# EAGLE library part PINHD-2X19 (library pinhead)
PIN HEADER
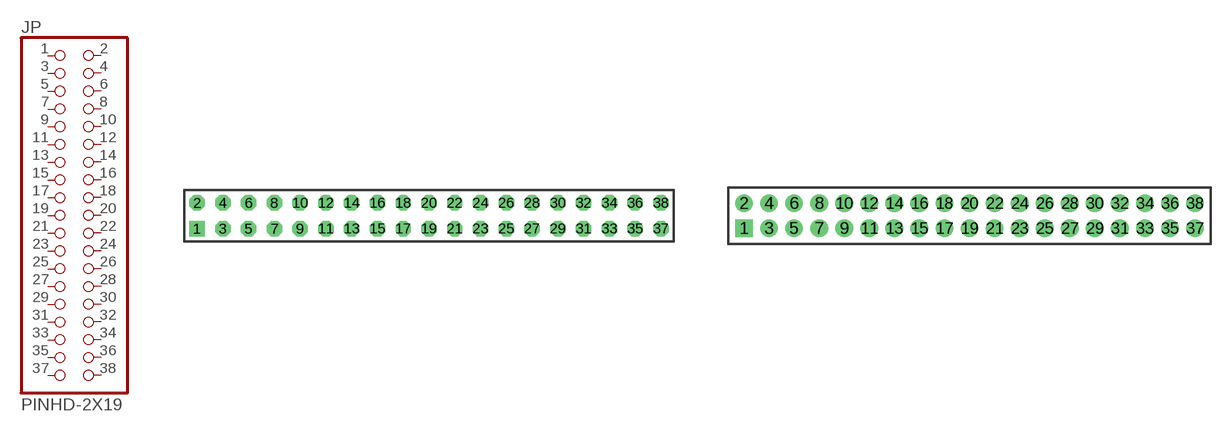
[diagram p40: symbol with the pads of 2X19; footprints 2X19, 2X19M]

Designator prefix JP

## PINHD-2X19  [2X19]
1  1  pas
2  2  pas
3  3  pas
4  4  pas
5  5  pas
6  6  pas
7  7  pas
8  8  pas
9  9  pas
10  10  pas
11  11  pas
12  12  pas
13  13  pas
14  14  pas
15  15  pas
16  16  pas
17  17  pas
18  18  pas
19  19  pas
20  20  pas
21  21  pas
22  22  pas
23  23  pas
24  24  pas
25  25  pas
26  26  pas
27  27  pas
28  28  pas
29  29  pas
30  30  pas
31  31  pas
32  32  pas
33  33  pas
34  34  pas
35  35  pas
36  36  pas
37  37  pas
38  38  pas

## PINHD-2X19M  [2X19M]
Pads as for 2X19

## Footprint 2X19 (pad centres in mm)
PIN HEADER - 0.1"
drill 1.016 square: 1 -22.86,-1.27
drill 1.016 octagon: 2 -22.86,1.27; 3 -20.32,-1.27; 4 -20.32,1.27; 5 -17.78,-1.27; 6 -17.78,1.27; 7 -15.24,-1.27; 8 -15.24,1.27; 9 -12.7,-1.27; 10 -12.7,1.27; 11 -10.16,-1.27; 12 -10.16,1.27; 13 -7.62,-1.27; 14 -7.62,1.27; 15 -5.08,-1.27; 16 -5.08,1.27; 17 -2.54,-1.27; 18 -2.54,1.27; 19 0,-1.27; 20 0,1.27; 21 2.54,-1.27; 22 2.54,1.27; 23 5.08,-1.27; 24 5.08,1.27; 25 7.62,-1.27; 26 7.62,1.27; 27 10.16,-1.27; 28 10.16,1.27; 29 12.7,-1.27; 30 12.7,1.27; 31 15.24,-1.27; 32 15.24,1.27; 33 17.78,-1.27; 34 17.78,1.27; 35 20.32,-1.27; 36 20.32,1.27; 37 22.86,-1.27; 38 22.86,1.27

## Footprint 2X19M (pad centres in mm)
PIN HEADER - 2MM"
drill 0.914 square: 1 -18,-1
drill 0.914 round: 2 -18,1; 3 -16,-1; 4 -16,1; 5 -14,-1; 6 -14,1; 7 -12,-1; 8 -12,1; 9 -10,-1; 10 -10,1; 11 -8,-1; 12 -8,1; 13 -6,-1; 14 -6,1; 15 -4,-1; 16 -4,1; 17 -2,-1; 18 -2,1; 19 0,-1; 20 0,1; 21 2,-1; 22 2,1; 23 4,-1; 24 4,1; 25 6,-1; 26 6,1; 27 8,-1; 28 8,1; 29 10,-1; 30 10,1; 31 12,-1; 32 12,1; 33 14,-1; 34 14,1; 35 16,-1; 36 16,1; 37 18,-1; 38 18,1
